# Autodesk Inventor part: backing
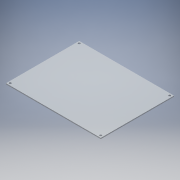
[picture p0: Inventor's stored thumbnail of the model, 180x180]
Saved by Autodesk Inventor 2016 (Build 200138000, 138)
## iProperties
Created: 2015-11
Part Number: backing
Material: Generic
Document SubType Name: Modeling
Designer: t_silvdo
Density: 1 g/cm^3
Appearance: Default
Author: t_silvdo
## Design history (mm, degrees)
sketch "Sketch2"
  geometry: L1 (0, 0)-(279.4, 0); L2 (279.4, 0)-(279.4, -215.9); L3 (279.4, -215.9)-(0, -215.9); L4 (0, -215.9)-(0, 0); C1 r 3.175 at (273.05, -6.35); C2 r 3.175 at (273.05, -209.55); C3 r 3.175 at (6.35, -6.35); C4 r 3.175 at (6.35, -209.55); 1 further point
  constraints: 8 end point, 4 centre point, 2 parallel, 1 horizontal, 1 perpendicular
  dimensions: "d7" = 279.4 distance of L2.end L3.end; "d8" = 215.9 distance of L1.end L2.end; "d9" = 6.35 diameter of C1; "d10" = 6.35 distance from line of C1.centre L1; "d11" = 6.35 distance from line of C1.centre L2
extrude "Extrusion2" new body sketch "Sketch2" distance "d12" = 3 (= acrylic); taper "d13" = 0 deg
body "Solid2"
other parameters: "acrylic" = 3 [user parameter; used in 1 equation term]
